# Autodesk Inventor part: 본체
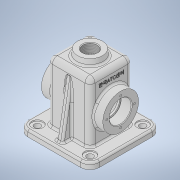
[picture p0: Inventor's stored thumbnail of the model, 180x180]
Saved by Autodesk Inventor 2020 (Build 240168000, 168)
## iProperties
Created: 2021-07
Part Number: 본체
Material: 일반
Document SubType Name: Modeling
Designer: Owner
Density: 1 g/cm^3
Appearance: 기본값
Mass: 278.257 g
Surface Area: 858.506 cm^2
Volume: 278.257 cm^3
Author: Owner
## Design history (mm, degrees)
sketch "스케치1"
  geometry: L1 (-34, -34)-(34, -34); L2 (34, -34)-(34, 34); L3 (34, 34)-(-34, 34); L4 (-34, 34)-(-34, -34); L5 (-34, -34)-(34, 34); L6 (34, -34)-(-34, 34); 1 further point
  constraints: 12 end point, 2 midpoint, 2 parallel, 1 horizontal, 1 perpendicular
  dimensions: "d0" = 68 distance of L3.end L2.end; "d1" = 68 distance of L2.end L1.end
extrude "돌출1" new body sketch "스케치1" stored distance "d2" = 105; taper "d3" = 0 deg
fillet "모깎기1" dims "d4" = 8
fillet "모깎기2" dims "d5" = 8
feature "쉘1" dims "d6" = 5
sketch "스케치3"
  geometry: L1 (57, -57)-(-57, -57); L2 (-57, -57)-(-57, 57); L3 (-57, 57)-(57, 57); L4 (57, 57)-(57, -57); L5 (57, -57)-(-57, 57); L6 (-57, -57)-(57, 57); L7 (29, 26)-(29, -26) reference; L8 (26, -29)-(-26, -29) reference; L9 (-29, -26)-(-29, 26) reference; L10 (-26, 29)-(26, 29) reference; L11 (26, 34)-(-26, 34) reference; L12 (-34, 26)-(-34, -26) reference; L13 (-26, -34)-(26, -34) reference; L14 (34, -26)-(34, 26) reference; A1 r 3 centre (26, 26) between (29, 26) and (26, 29) reference; A2 r 3 centre (26, -26) between (26, -29) and (29, -26) reference; A3 r 3 centre (-26, -26) between (-29, -26) and (-26, -29) reference; A4 r 3 centre (-26, 26) between (-26, 29) and (-29, 26) reference; A5 r 8 centre (26, 26) between (34, 26) and (26, 34) reference; A6 r 8 centre (-26, 26) between (-26, 34) and (-34, 26) reference; A7 r 8 centre (-26, -26) between (-34, -26) and (-26, -34) reference; A8 r 8 centre (26, -26) between (26, -34) and (34, -26) reference; 1 further point
  constraints: 12 end point, 2 midpoint, 2 parallel, 1 horizontal, 1 perpendicular
  dimensions: "d9" = 114 distance of L2.end L3.end; "d10" = 114 distance of L1.end L2.end
extrude "돌출2" join sketch "스케치3" distance "d11" = 10; taper "d12" = 0 deg
fillet "모깎기3" dims "d13" = 15
fillet "모깎기4" dims "d14" = 15
node "작업 평면1"
sketch "스케치4"
  geometry: L1 (68, -97)-(-16, -97) reference; C1 r 28.5 at (26, -45); 1 further point
  constraints: 1 centre point, 1 vertical alignment
  dimensions: "d16" = 57 diameter of C1; "d17" = 52 distance from line of C1.centre L1
extrude "돌출3" join sketch "스케치4" stored distance "d18" = 10; taper "d19" = 0 deg
sketch "스케치5"
  geometry: C1 r 28.5 at (0, 0) reference; 2 further points
  constraints: 1 coincident
hole "구멍1" sketch "스케치5" at (0, 0) diameter "d20" = 35; stored, may be unused: countersink angle "d24" = 90 deg, drill point angle "d26" = 0 deg; dims "d21" = 20, "d22" = 4, "d23" = 2, "d25" = 17
sketch "스케치6"
  geometry: C1 r 17.5 at (0, 0) reference; 2 further points
  constraints: 1 coincident
hole "구멍2" sketch "스케치6" at (0, 0) diameter "d27" = 30; stored, may be unused: countersink angle "d31" = 90 deg, drill point angle "d33" = 0 deg; dims "d28" = 20, "d29" = 4, "d30" = 2, "d32" = 132.5
node "작업 평면2"
sketch "스케치7"
  geometry: C1 r 20 at (0, 0); 1 further point
  constraints: 1 centre point, 1 coincident
  dimensions: "d35" = 40 diameter of C1
extrude "돌출4" join sketch "스케치7" stored distance "d36" = 10; taper "d37" = 8 deg
sketch "스케치8"
  geometry: C1 r 20 at (0, 0) reference; 2 further points
  constraints: 1 coincident
hole "구멍3" sketch "스케치8" at (0, 0) diameter "d38" = 22.83494; stored, may be unused: countersink angle "d42" = 90 deg, drill point angle "d44" = 0 deg; dims "d39" = 50, "d40" = 4, "d41" = 2, "d43" = 59.3
sketch "스케치9"
  geometry: C1 r 15 at (0, 0) reference; 2 further points
  constraints: 1 vertical alignment
  dimensions: "d45" = 22 distance of point (0, 22) C1.centre
hole "구멍4" sketch "스케치9" at (0, 22) diameter "d46" = 3.242; stored, may be unused: countersink angle "d50" = 90 deg, drill point angle "d52" = 118 deg; dims "d47" = 8, "d48" = 4, "d49" = 2, "d51" = 10
sketch "스케치10"
  geometry: A1 r 15 centre (-42, 42) between (-42, 57) and (-57, 42) reference; 1 further point
hole "구멍5" sketch "스케치10" at (-42, 42) diameter "d56" = 10; stored, may be unused: countersink angle "d60" = 90 deg, drill point angle "d62" = 0 deg; dims "d57" = 8, "d58" = 18, "d59" = 2, "d61" = 35
sketch "스케치11"
  geometry: L1 (-49, -42.5)-(-34, 42.569); L2 (34, 42.569)-(49, -42.5); L3 (-51, -42.5)-(-33, -42.5) reference; L4 (-57, -52.5)-(-57, -42.5) reference; L5 (-34, -42.5)-(-34, 44.5) reference; L6 (33, -42.5)-(51, -42.5) reference; L7 (57, -42.5)-(57, -52.5) reference; L8 (34, 44.5)-(34, -42.5) reference; 1 further point
  constraints: 4 end point, 4 point on line
  dimensions: "d63" = 8 distance from line of L1.start L4; "d64" = 10 deg angle of L1 L4; "d65" = 8 distance from line of L7 L2.end; "d66" = 10 deg angle of L7 L2
sketch "스케치12"
  geometry: L1 (46, 18)-(6, 18) reference; 2 further points
  constraints: 1 vertical alignment, 1 other
  dimensions: "d67" = 25 distance from line of point (26, -7) L1
extrude "돌출5" join sketch "스케치11" stored distance "d68" = 10; taper "d69" = 0 deg
feature "엠보싱1" dims "d70" = 0.5, "d71" = 0
fillet "모깎기5" dims "d72" = 3
fillet "모깎기7" dims "d74" = 3
fillet "모깎기8" dims "d75" = 3
fillet "모깎기9" dims "d76" = 3
fillet "모깎기10" dims "d77" = 3
fillet "모깎기11" dims "d78" = 3
fillet "모깎기12" dims "d79" = 3
chamfer "모따기1" distance "d80" = 1; stored, may be unused: second distance "d81" = 2, angle "d82" = 45 deg
fillet "모깎기13" dims "d83" = 0.3
node "솔리드1"
mirror "미러1"
mirror "미러2"
pattern_circular "원형 패턴1" dims angle "d54" = 360 deg
mirror "미러3"
mirror "미러4"
mirror "미러5"
node "투영된 루프1"
feature "A9D066F2-1C7D-4E18-AEED-F7BC21143FA4" dims "d20" = 35, "d21" = 20, "d22" = 4, "d23" = 2, "d24" = 90 deg, "d25" = 17, "d26" = 0
other parameters: "d15" = 15, "d34" = -115
